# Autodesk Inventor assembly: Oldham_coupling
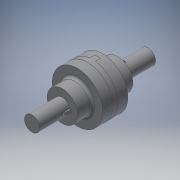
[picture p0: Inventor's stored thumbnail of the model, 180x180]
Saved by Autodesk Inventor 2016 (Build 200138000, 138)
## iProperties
Created: 2020-03
Part Number: Oldham_coupling
Document SubType Name: Assembly
Designer: Furqan
Author: Furqan
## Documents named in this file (3)
- C:\Users\Furqan\Desktop\Autodesk Inventor\Autodesk Inventor 2016 Learn by doing - Tutorial Books\C3T1. Oldham Coupling.iam
- C:\Users\Furqan\Desktop\Autodesk Inventor\Autodesk Inventor 2016 Learn by doing - Tutorial Books\C2T1. Disc.ipt
- C:\Users\Furqan\Desktop\Autodesk Inventor\Autodesk Inventor 2016 Learn by doing - Tutorial Books\C3T1. Flange_subassembly.iam
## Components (3 placed, 2 different names)
1. C2T1. Disc:1 — Insert:1, Mate:1, Insert:2, Mate:2
2. C3T1. Flange_subassembly:1 [sub-assembly] — Insert:1, Mate:1
3. C3T1. Flange_subassembly:2 [sub-assembly] — Insert:2, Mate:2
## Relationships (4: Insert 2, Mate 2)
- Insert:1: C2T1. Disc:1 ↔ C3T1. Flange_subassembly:1
- Mate:1: C2T1. Disc:1 ↔ C3T1. Flange_subassembly:1
- Insert:2: C2T1. Disc:1 ↔ C3T1. Flange_subassembly:2
- Mate:2: C2T1. Disc:1 ↔ C3T1. Flange_subassembly:2
